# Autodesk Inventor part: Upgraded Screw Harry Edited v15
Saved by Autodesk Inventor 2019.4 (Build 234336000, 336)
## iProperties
Created: 2020-06
Part Number: Upgraded Screw Harry Edited v15
Material: Generic
Document SubType Name: Modeling
Designer: Administrator
Density: 1 g/cm^3
Appearance: Default
Title: Upgraded Screw Harry Edited v15
Author: Administrator
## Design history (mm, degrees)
